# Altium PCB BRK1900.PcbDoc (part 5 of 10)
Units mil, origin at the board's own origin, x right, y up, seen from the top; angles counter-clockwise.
Board outline 8858.27 x 5905.51 mil, 10 copper layers (L1-TOP, L2-GND, L3-SIG1, L4-GND, L5-PWR, L6-PWR, L7-GND, L8-SIG2, L9-GND, L10-BOT), stack 48.824 mil thick; 507 components, 607 nets, 2498 pads, 2210 vias.
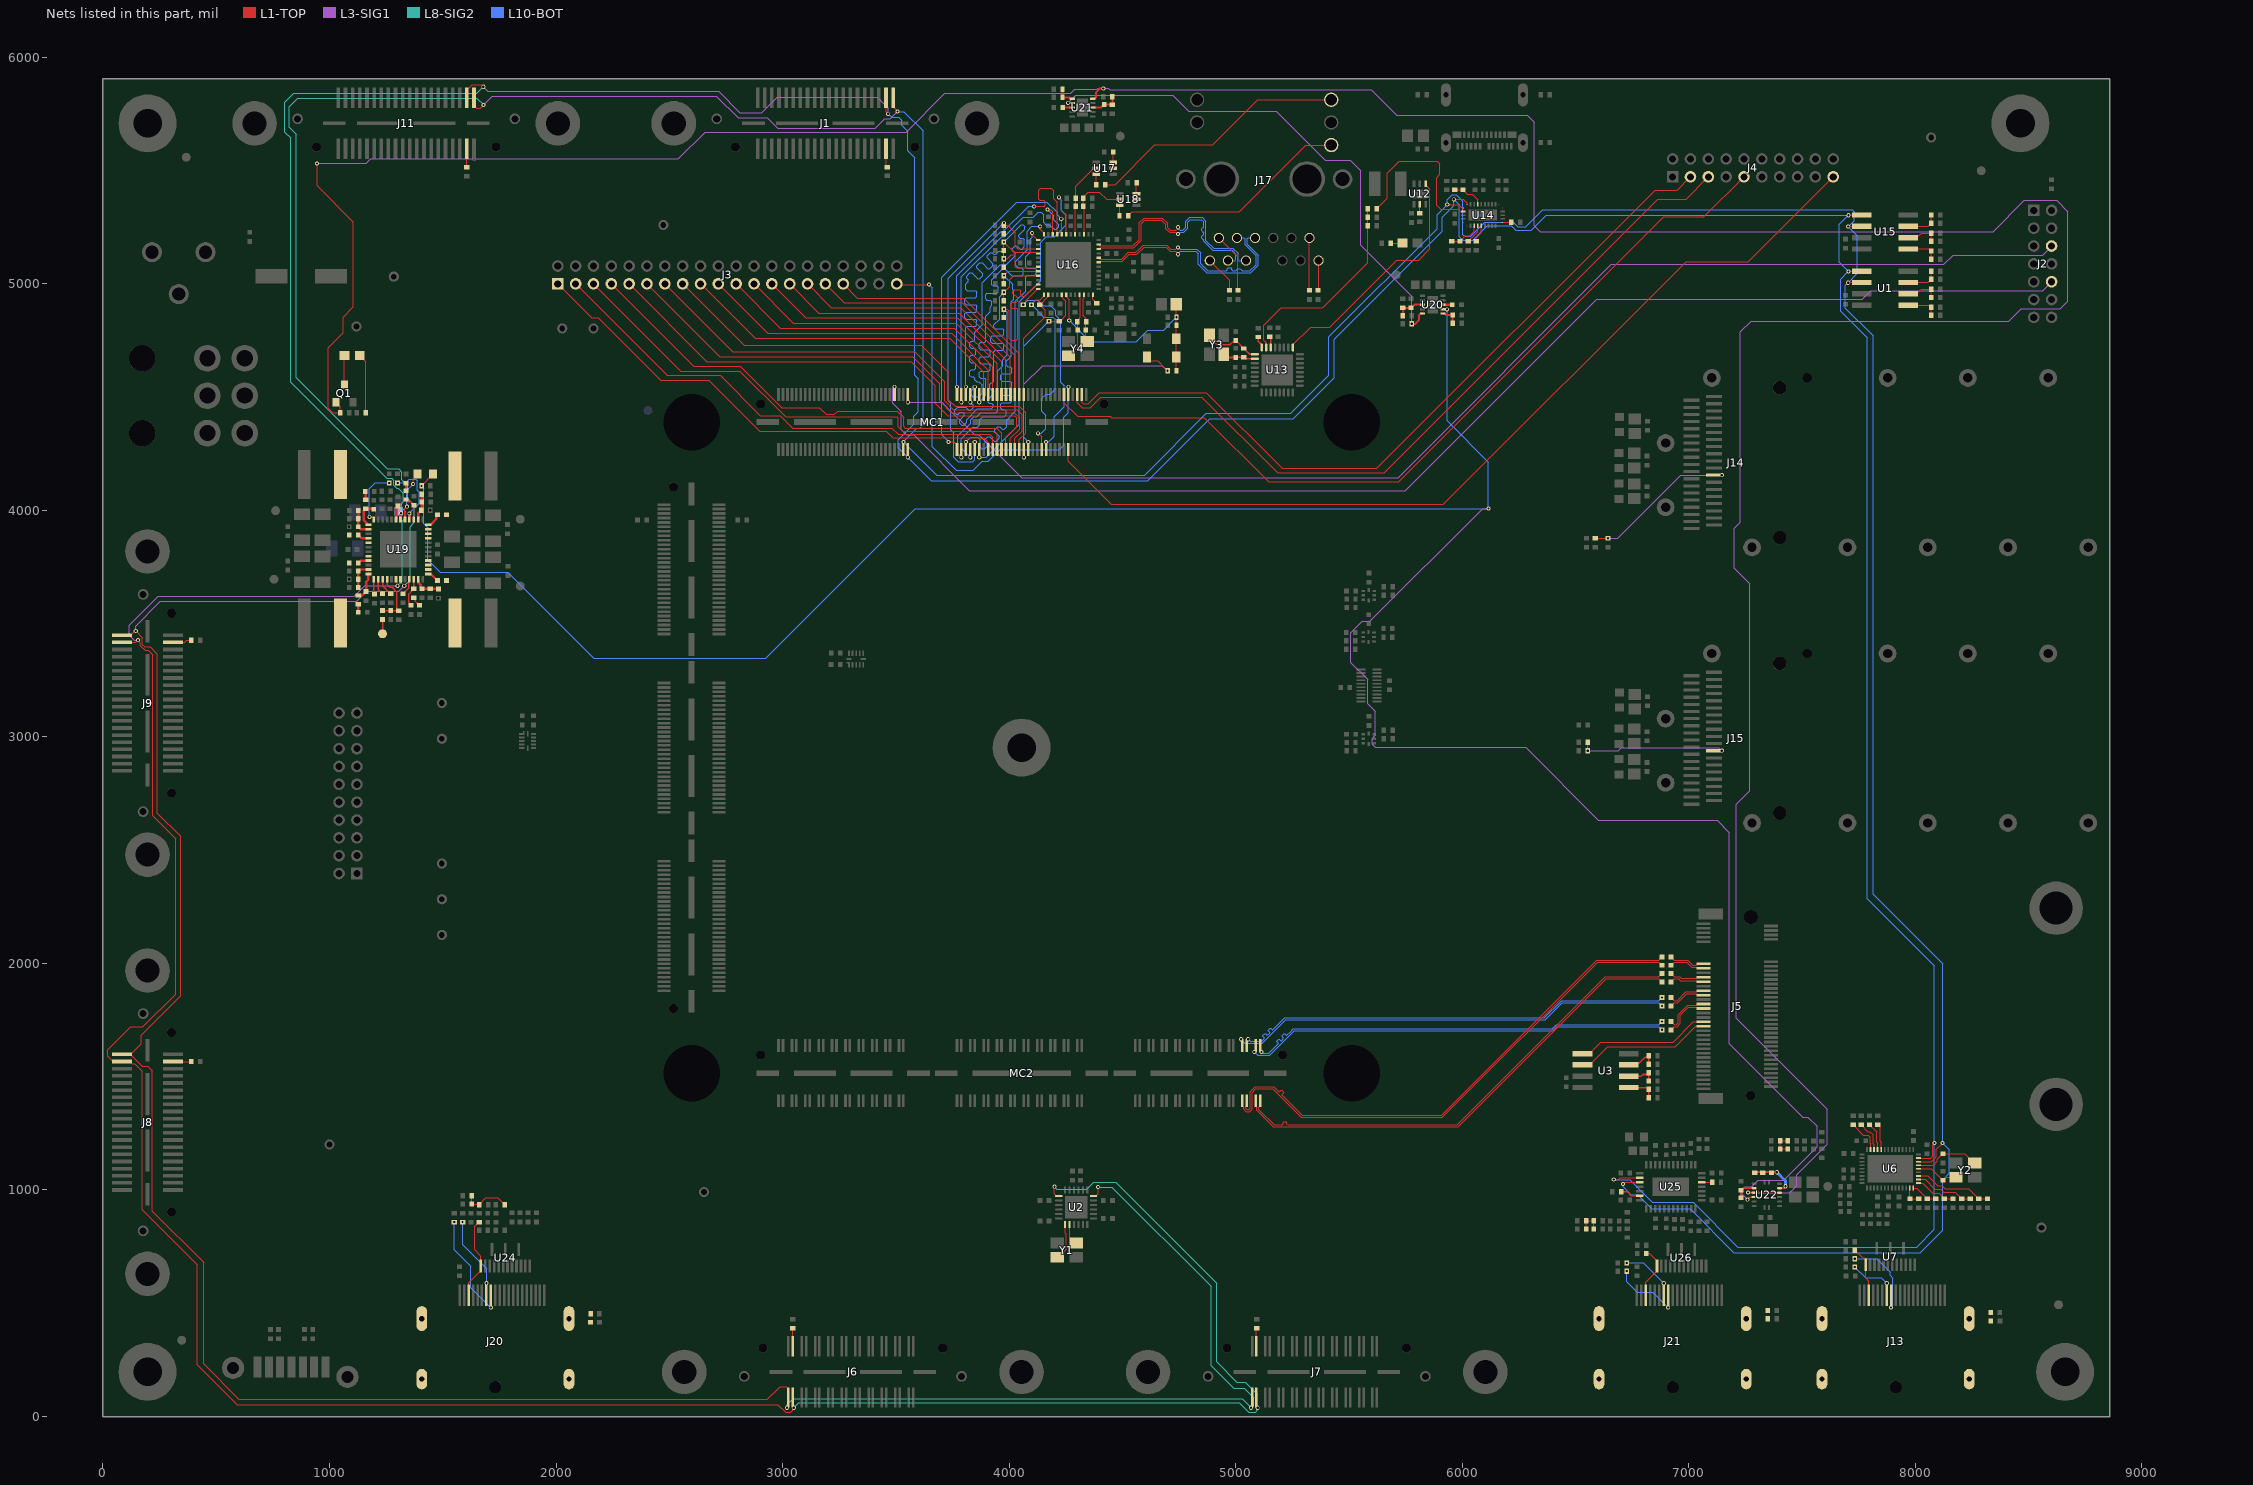
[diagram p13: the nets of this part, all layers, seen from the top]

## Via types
v1: diameter 18, hole 10, L1-TOP to L10-BOT, tented both sides, 2210 vias

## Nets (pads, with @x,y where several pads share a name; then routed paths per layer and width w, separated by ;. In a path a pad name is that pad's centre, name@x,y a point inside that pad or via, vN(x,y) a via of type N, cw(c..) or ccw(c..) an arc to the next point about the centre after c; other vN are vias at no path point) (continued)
ETH_TXRX_C_N: J17.2 U16.8 | length 1009.5
  L1-TOP w3.3: U16.8@4395.76,5114.81 4401.1,5109.47 4496.47,5109.47 4526,5139 4559.81,5139 4574.29,5153.48 4587.54,5166.73 4591.81,5171 4697,5171 4714.52,5153.48 4736.72,5153.48 v1@4746,5162.76
  L10-BOT w3.3: v1@4746,5162.76 4755.28,5153.48 4828.24,5153.48 4845,5136.73 4845,5089.25 4876.11,5058.15 4957.91,5058.15 4959.57,5058.15 4963.63,5062.21 4963.63,5066.09 4967.69,5070.15 4979.87,5070.15 4983.93,5066.09 4983.93,5062.21 4987.99,5058.15 5000.17,5058.15 5004.23,5062.21 5004.23,5063.45 5008.29,5067.51 5020.47,5067.51 5024.53,5063.45 5024.53,5062.21 5028.59,5058.15 5050,5058.15 5063.15,5058.15 5090,5085 5090,5123.27 5041.5,5171.77 5041.5,5198 5036.9,5202.6 J17.2@5006,5202.6
  other v1: 4746,5160.56
ETH_TXRX_C_P: J17.3 U16.7 | length 1000.7
  L1-TOP w3.3: U16.7@4395.76,5095.12 4401.1,5100.47 4500.19,5100.47 4529.73,5130 4563.54,5130 4595.54,5162 4693.27,5162 4710.79,5144.48 4736.72,5144.48 v1@4746,5135.2
  L10-BOT w3.3: v1@4746,5135.2 4755.28,5144.48 4824.52,5144.48 4836,5133 4836,5085.53 4872.38,5049.15 5066.87,5049.15 5099,5081.27 5099,5127 5050.5,5175.5 5050.5,5198 5055.1,5202.6 J17.3@5086,5202.6
  other v1: 4746,5130.8
ETH_TXRX_D_N: J17.9 U16.11 | length 972
  L1-TOP w3.3: U16.11@4395.76,5173.86 4401.1,5168.52 4546.79,5168.52 4574,5195.73 4574,5268.8 4595.71,5290.51 4676.13,5290.51 4700,5266.64 4700,5248 4711.84,5236.16 4736.72,5236.16 v1@4746,5245.44
  L10-BOT w3.3: v1@4746,5245.44 4755.28,5236.16 4767,5236.16 4780,5249.16 4780,5271.73 4780,5276.13 4796.86,5292.99 4801.26,5292.99 4846.74,5292.99 4852.98,5292.99 4869,5276.97 4869,5270.73 4869,5191 4903,5157 4987.73,5157 5010.5,5134.23 5010.5,5106 5013.9,5102.6 J17.9@5046,5102.6
  other v1: 4746,5249.84
ETH_TXRX_D_P: J17.8 U16.10 | length 980.8
  L1-TOP w3.3: U16.10@4395.76,5154.18 4401.1,5159.52 4550.52,5159.52 4583,5192 4583,5265.07 4599.44,5281.51 4672.4,5281.51 4691,5262.91 4691,5244.27 4708.11,5227.16 4736.72,5227.16 v1@4746,5217.88
  L10-BOT w3.3: v1@4746,5217.88 4755.28,5227.16 4770.73,5227.16 4789,5245.43 4789,5272.4 4800.58,5283.99 4849.25,5283.99 4860,5273.24 4860,5268 4860,5250.05 4856.74,5246.79 4853.26,5246.79 4850,5243.53 4850,5233.75 4853.26,5230.49 4856.74,5230.49 4860,5227.23 4860,5217.45 4856.74,5214.19 4853.77,5214.19 4850.51,5210.93 4850.51,5201.15 4853.77,5197.89 4856.74,5197.89 4860,5194.63 4860,5192.54 4860,5187.27 4899.27,5148 4984,5148 5001.5,5130.5 5001.5,5106 4998.1,5102.6 J17.8@4966,5102.6
  other v1: 4746,5220.08
FPX1301_RXN0: C15.1 MC2.120 | length 2145.7
  L1-TOP w3.3: MC2.120@5108.27,1394.09 5108.27,1371.48 5102.92,1366.14 5102.92,1355 5169.93,1288 5194,1288 5207.88,1288 5210.33,1290.45 5210.33,1299.1 5212.77,1301.54 5224.18,1301.54 5226.63,1299.1 5226.63,1290.45 5229.07,1288 5247.02,1288 5979.27,1288 6632.27,1941 6867.92,1941 C15.1@6881.92,1955
FPX1301_RXN0_C: C15.2 J5.51 | length 154.9
  L1-TOP w3.3: C15.2@6922.08,1955 6936.08,1941 6959.73,1941 6967.09,1933.63 7035.94,1933.63 7041.29,1938.98 J5.51@7065.94,1938.98
FPX1301_RXN1: C17.1 MC2.116 | length 2325.1
  L1-TOP w3.3: MC2.116@5049.21,1394.09 5049.21,1371.31 5043.87,1365.97 5043.87,1360 5050.22,1353.65 5057.65,1353.65 5064,1360 5064,1433.73 5085.64,1455.37 5168.63,1455.37 5186.5,1437.5 5190.32,1433.68 5193.78,1433.68 5199.9,1439.79 5203.36,1439.79 5211.43,1431.73 5211.43,1428.27 5205.31,1422.15 5205.31,1418.69 5218,1406 5294,1330 5909.27,1330 6594.27,2015 6867.92,2015 C17.1@6881.92,2029
FPX1301_RXN1_C: C17.2 J5.57 | length 161.1
  L1-TOP w3.3: C17.2@6922.08,2029 6936.08,2015 6995.69,2015 7018,1992.69 7035.77,1992.69 7041.11,1998.03 J5.57@7065.94,1998.03
FPX1301_RXP0: C14.1 MC2.118 | length 2139.2
  L1-TOP w3.3: MC2.118@5088.58,1394.09 5088.58,1370.89 5093.92,1365.54 5093.92,1351.27 5153.2,1292 5166.2,1279 5983,1279 5996,1292 6636,1932 6867.92,1932 C14.1@6881.92,1918
FPX1301_RXP0_C: C14.2 J5.49 | length 154.9
  L1-TOP w3.3: C14.2@6922.08,1918 6936.08,1932 6956,1932 6963.37,1924.63 7035.71,1924.63 7041.05,1919.29 J5.49@7065.94,1919.29
FPX1301_RXP1: C16.1 MC2.114 | length 2318.7
  L1-TOP w3.3: MC2.114@5029.53,1394.09 5029.53,1371.06 5034.87,1365.71 5034.87,1356.27 5046.49,1344.65 5061.38,1344.65 5073,1356.27 5073,1430 5089.37,1446.37 5164.9,1446.37 5268.27,1343 5290.27,1321 5913,1321 5935,1343 6598,2006 6867.92,2006 C16.1@6881.92,1992
FPX1301_RXP1_C: C16.2 J5.55 | length 161.1
  L1-TOP w3.3: C16.2@6922.08,1992 6936.08,2006 6991.96,2006 7014.27,1983.69 7035.54,1983.69 7040.88,1978.35 J5.55@7065.94,1978.35
FPX1301_TXN0: C11.1 MC2.119 | length 1871.5
  L10-BOT w3.3: v1(5114.17,1609.4) 5120.61,1602.97 5146.24,1602.97 5186.64,1643.36 5187.8,1644.53 5187.8,1647.99 5181.69,1654.11 5181.69,1657.56 5189.75,1665.63 5193.21,1665.63 5199.33,1659.51 5202.79,1659.51 5210.85,1667.58 5210.85,1671.04 5204.74,1677.16 5204.74,1680.62 5212.8,1688.68 5216.26,1688.68 5222.38,1682.57 5225.84,1682.57 5233.3,1690.03 5238.27,1695 5255.27,1712 6397.27,1712 6415.28,1730.01 6867.92,1730.01 v1(6881.92,1744.01)
FPX1301_TXN0_C: C11.2 J5.39 | length 208
  L1-TOP w3.3: C11.2@6922.08,1744.01 6936.08,1730.01 6945.04,1730.01 6954,1738.97 6954,1774.36 6995.16,1815.52 7036.38,1815.52 7041.72,1820.87 J5.39@7065.94,1820.87
FPX1301_TXN1: C13.1 MC2.115 | length 1952.7
  L10-BOT w3.3: v1(5055.12,1665.4) 5063.52,1657 5114.27,1657 5125.64,1668.36 5126.8,1669.53 5126.8,1672.99 5120.69,1679.11 5120.69,1682.56 5128.75,1690.63 5132.21,1690.63 5138.33,1684.51 5141.79,1684.51 5149.85,1692.58 5149.85,1696.04 5143.74,1702.16 5143.74,1705.62 5151.8,1713.68 5155.26,1713.68 5161.38,1707.57 5164.84,1707.57 5174.64,1717.36 5206.27,1749 5217.27,1760 6363.27,1760 6438.78,1835.5 6867.92,1835.5 v1(6881.92,1849.5)
FPX1301_TXN1_C: C13.2 J5.45 | length 168.1
  L1-TOP w3.3: C13.2@6922.08,1849.5 6936.08,1835.5 6948.5,1835.5 6987.58,1874.58 7035.77,1874.58 7041.11,1879.92 J5.45@7065.94,1879.92
FPX1301_TXP0: C10.1 MC2.117 | length 1864.1
  L10-BOT w3.3: v1(5082.68,1609.4) 5098.11,1593.97 5149.97,1593.97 5259,1703 6401,1703 6419.01,1721.01 6867.92,1721.01 v1(6881.92,1707.01)
FPX1301_TXP0_C: C10.2 J5.37 | length 208
  L1-TOP w3.3: C10.2@6922.08,1707.01 6936.08,1721.01 6948.77,1721.01 6963,1735.24 6963,1770.63 6998.89,1806.52 7035.53,1806.52 7040.87,1801.18 J5.37@7065.94,1801.18
FPX1301_TXP1: C12.1 MC2.113 | length 1945.2
  L10-BOT w3.3: v1(5023.62,1665.4) 5041.02,1648 5118,1648 5221,1751 6367,1751 6442.5,1826.5 6867.92,1826.5 v1(6881.92,1812.5)
FPX1301_TXP1_C: C12.2 J5.43 | length 168.1
  L1-TOP w3.3: C12.2@6922.08,1812.5 6936.08,1826.5 6952.23,1826.5 6991.31,1865.58 7035.62,1865.58 7040.96,1860.24 J5.43@7065.94,1860.24
FPX_EEPROM_SCL: J5.29 U3.6 | length 605.2
  L1-TOP w5: U3.6@6531.24,1552.15 6563.7,1552.15 6643.55,1632 6941,1632 7031.44,1722.44 J5.29@7065.94,1722.44
FPX_EEPROM_SDA: J5.31 U3.5 | length 592.7
  L1-TOP w5: U3.5@6531.24,1602.15 6561.15,1602.15 6612,1653 6931,1653 7020.13,1742.13 J5.31@7065.94,1742.13
GIGE_INT_B: MC1.91 R107.1 U16.38 | length 505.2
  L1-TOP w5: MC1.91@4064.96,4511.42 4064.96,4759.96 4160,4855 4160,4883.69 R107.1@4136,4907.69 4136.69,4907.69 4173.32,4944.32 U16.38@4173.32,4951.42
GIGE_LED1: R110.1 R115.2 U16.17 U17.2 | length 335.9
  L1-TOP w5: U16.17@4291.43,5219.14 4291.43,5338.82 R110.1@4294.74,5342.14 R115.2@4294.74,5378.14 4294.74,5430.74 4374,5510 U17.2@4384.83,5510
GIGE_LED2: R111.1 R116.2 U16.15 U18.2 | length 347.8
  L1-TOP w5: U16.15@4330.8,5219.14 4330.8,5338.4 R111.1@4327.06,5342.14 R116.2@4327.06,5378.14 4327.06,5382.06 4350,5405 4398,5405 4430,5373 U18.2@4487.6,5373
GIGE_LED_MODE: MC1.94 R108.1 R114.2 U16.41 | length 770.5
  L1-TOP w5: R108.1@4176,4834.69 v1(4176.14,4834.82) R114.2@4222.06,4834.82 4224.03,4834.82 4231.37,4842.17 4251.06,4861.86 4251.06,4923.14 4234.8,4939.4 4234.8,4949 U16.41@4232.37,4951.42
  L10-BOT w5: v1(4084.65,4302.11) 4065,4321.76 4065,4723.69 v1(4176.14,4834.82)
GIGE_MDC: MC1.102 R105.1 U16.36 | length 905.1
  L1-TOP w4.55: v1(4062,4907.69) 4073,4918.69 4073,4926 4124.01,4977.01 U16.36@4128.04,4977.01
  L10-BOT w4.55: v1(4062,4907.69) 4081.46,4927.14 4126.86,4927.14 4151,4903 4184,4903 4205,4882 4205,4861 4229,4837 4229,4724 4229,4566.1 4244,4551.1 4244,4457 4200,4413 4200,4327 4175.11,4302.11 v1(4163.39,4302.11)
GIGE_MDIO: MC1.100 R106.1 U16.37 | length 852
  L1-TOP w4.55: v1(4099,4907.69) 4120.87,4929.55 4137.55,4929.55 4153.63,4945.63 U16.37@4153.63,4951.42 ; v1(4127.84,4340.27) 4143.7,4324.41 MC1.100@4143.7,4268.11
  L10-BOT w4.55: v1(4099,4907.69) 4153.69,4853 4193,4853 4203,4843 4203,4535 4181,4513 4163,4513 4144,4494 4144,4438 4161,4421 4161,4360 4141.27,4340.27 v1(4127.84,4340.27)
GIGE_RESET_B: D3.2 MC1.92 R117.1 | length 1117.1
  L1-TOP w4.55: D3.2@4608.72,4676.57 4624.72,4660.57 4655.6,4660.57 4690.29,4625.89 4692.26,4625.89 4699.6,4618.54 v1(4699.6,4616.57)
  L3-SIG1 w4.05: v1(4064.96,4234.11) 4064.96,4555.96 4148,4639 4677.17,4639 v1(4699.6,4616.57)
GIGE_RX_CLK: MC1.64 R91.1 R99.2 U16.35 | length 1452.9
  L1-TOP w4.55: R99.2@3977.17,4851.42 v1(3977.17,4888.42) 3991.58,4888.42 4001,4879 4001,4759 4009,4751 4032,4751 4038,4757 4038,4887 4033,4892 4015,4892 4008,4899 4008,4913 4013,4918 4032,4918 4038,4924 4038,4938.04 4017,4959.04 4017,4966 4026,4975 4046,4975 4052,4969 4052,4952 4058,4946 4070,4946 4120.7,4996.7 U16.35@4128.04,4996.7
  L10-BOT w4.55: v1(3789.37,4234.11) 3774,4249.48 3774,4329 3830,4385 3830,4400 3844,4414 3857.16,4414 3874.58,4431.42 3940.42,4431.42 3949,4440 3949,4616 3971,4638 3971,4666 3992,4687 3992,4873.59 v1(3977.17,4888.42)
GIGE_RX_DV: MC1.67 R90.1 R98.2 U16.33 | length 1416
  L1-TOP w4.55: R98.2@3977.17,4925.42 v1(3977.17,4962.42) 4002,4987.25 4002,5018 4020.07,5036.07 U16.33@4128.04,5036.07
  L10-BOT w4.55: v1(3828.74,4477.42) 3841,4465.16 3841,4453 3831,4443 3821,4443 3808,4456 3773,4456 3761,4444 3761,4429 3766,4424 3774.5,4424 3784.5,4434 3797,4434 3803,4428 3803,4420 3782,4399 3782,4384 3791,4375 3799,4375 3813,4389 3813,4401 3860,4448 3921,4448 3930,4457 3930,4467 3923,4474 3912,4474 3908.19,4477.81 3908.19,4489.81 3933,4514.62 3933,4519.13 3933,4525.98 3926.69,4532.29 3921.45,4532.29 3915.14,4538.6 3915.14,4557.53 3921.45,4563.84 3926.69,4563.84 3933,4570.15 3933,4603.97 3933,4693.33 3933,4700.81 3939.31,4707.12 3971.04,4707.12 3977.35,4713.43 3977.35,4732.36 3971.04,4738.67 3926.16,4738.67 3919.85,4744.98 3919.85,4763.91 3926.16,4770.23 3971.04,4770.23 3977.35,4776.53 3977.35,4795.47 3971.04,4801.77 3939.31,4801.77 3933,4808.08 3933,4810.36 3933,4819 3958,4844 3958,4943.25 v1(3977.17,4962.42)
GIGE_RXD0: MC1.68 R95.1 R103.2 U16.32 | length 1433.7
  L1-TOP w4.55: R103.2@3977.31,4999.68 3977.31,5036.28 v1(3977.17,5036.42) 3996.5,5055.75 U16.32@4128.04,5055.75
  L10-BOT w4.55: v1(3828.74,4234.11) 3787.88,4274.97 3787.88,4315.88 3839,4367 3859,4367 3870,4378 3870,4399.26 3883.87,4413.13 3979.13,4413.13 3988,4422 3988,4436 3988,4438.28 3981.69,4444.59 3970.31,4444.59 3964,4450.9 3964,4469.83 3970.31,4476.14 4005.69,4476.14 4012,4482.45 4012,4501.38 4005.69,4507.69 3970.31,4507.69 3964,4514 3964,4532.93 3970.31,4539.24 4005.69,4539.24 4012,4545.55 4012,4564.48 4005.69,4570.79 3970.31,4570.79 3964,4577.1 3964,4596.03 3970.31,4602.34 4005.69,4602.34 4012,4608.65 4012,4627.58 4005.69,4633.89 3994.31,4633.89 3988,4640.2 3988,4650 3988,4658 4010,4680 4010,4921.65 4021.31,4932.95 4021.31,4969.29 4016,4974.59 4016,4997.59 v1(3977.17,5036.42)
GIGE_RXD1: MC1.65 R94.1 R102.2 U16.31 | length 1420.3
  L1-TOP w4.55: R102.2@3977.07,5073.41 R94.1@3977.07,5110.33 ; v1(3977.17,5110.42) 3991.42,5110.42 4009,5128 4021,5128 4028,5121 4028,5075 4032,5071 4118,5071 4122.44,5075.44 U16.31@4128.04,5075.44
  L10-BOT w4.55: v1(3809.05,4545.42) 3809.05,4772.24 3809.05,4806.06 3815.36,4812.37 3851.94,4812.37 3858.25,4818.68 3858.25,4837.61 3851.94,4843.92 3811.64,4843.92 3805.33,4850.23 3805.33,4869.16 3811.64,4875.47 3851.94,4875.47 3858.25,4881.78 3858.25,4900.71 3851.94,4907.02 3811.64,4907.02 3805.33,4913.33 3805.33,4932.26 3811.64,4938.57 3851.94,4938.57 3858.25,4944.88 3858.25,4963.81 3851.94,4970.12 3815.36,4970.12 3809.05,4976.43 3809.05,4983.72 3809.05,4999.05 3818.5,5008.5 3820.11,5010.11 3820.11,5019.03 3813.48,5025.67 3813.48,5034.59 3826.86,5047.97 3835.79,5047.97 3861.47,5022.29 3870.39,5022.29 3883.78,5035.68 3883.78,5044.6 3858.09,5070.28 3858.09,5079.21 3871.48,5092.59 3880.4,5092.59 3906.09,5066.91 3915.01,5066.91 3928.39,5080.3 3928.39,5089.22 3902.71,5114.9 3902.71,5123.83 3916.1,5137.21 3925.02,5137.21 3931.65,5130.58 3940.58,5130.58 3948,5138 3954,5144 3971,5144 3977.17,5137.83 v1(3977.17,5110.42)
GIGE_RXD2: MC1.69 R93.1 R101.2 U16.28 | length 1480.4
  L1-TOP w4.55: v1(3977.17,5184.42) 3977.32,5184.42 4021.75,5140 4115,5140 4120.51,5134.49 U16.28@4128.04,5134.49 ; R101.2@3977.26,5147.41 R93.1@3977.26,5184.34
  L10-BOT w4.55: v1(3848.42,4545.42) 3832,4528.99 3832,4510 3840,4502 3865,4502 3881,4518 3881,4554 3867.12,4567.88 3857.77,4567.88 3848.42,4577.23 3848.42,4577.75 3848.42,4582.8 3842.11,4589.11 3832.73,4589.11 3826.42,4595.42 3826.42,4614.35 3832.73,4620.66 3846.51,4620.66 3852.82,4626.97 3852.82,4645.9 3846.51,4652.21 3832.73,4652.21 3826.42,4658.52 3826.42,4677.45 3832.73,4683.76 3846.51,4683.76 3852.82,4690.07 3852.82,4709 3846.51,4715.31 3832.73,4715.31 3826.42,4721.62 3826.42,4740.55 3832.73,4746.86 3842.11,4746.86 3848.42,4753.17 3848.42,4787 3881,4819.58 3881,5005 3960,5084 3988,5084 4027.5,5123.5 4027.5,5135.5 4013.75,5149.25 4013.75,5154.75 4026.5,5167.5 4034.5,5167.5 4049,5153 4057,5153 4067,5163 4067,5195.5 4060.5,5202 4048,5202 4042,5208 4042,5215 4069,5242 4069,5253 4062,5260 4052.75,5260 v1(3977.17,5184.42)
GIGE_RXD3: MC1.70 R92.1 R100.2 U16.27 | length 1594.6
  L1-TOP w4.55: R100.2@3977.17,5221.42 R92.1@3977.17,5258.42 3994.58,5258.42 4027,5226 4027,5165 4037.82,5154.18 U16.27@4128.04,5154.18
  L10-BOT w4.55: v1(3848.42,4302.11) 3848.42,4224.42 3839.51,4215.51 3775.49,4215.51 3756,4235 3756,4343 3743,4356 3743,4474 3732,4485 3732,5024.3 v1(3977.16,5269.46)
GIGE_TX_CLK: MC1.71 U16.24 | length 1382.5
  L1-TOP w4.55: v1(4137.04,5253.5) 4137.04,5241.96 4153.63,5225.37 U16.24@4153.63,5219.14
  L10-BOT w4.55: v1(3868.11,4477.42) 3898,4507.31 3898,4575 3898,4577.28 3891.69,4583.59 3873.83,4583.59 3867.52,4589.9 3867.52,4608.83 3873.83,4615.14 3910.45,4615.14 3916.76,4621.45 3916.76,4640.38 3910.45,4646.69 3873.83,4646.69 3867.52,4653 3867.52,4671.93 3873.83,4678.24 3910.45,4678.24 3916.76,4684.55 3916.76,4703.48 3910.45,4709.79 3873.83,4709.79 3867.52,4716.1 3867.52,4735.03 3873.83,4741.34 3891.69,4741.34 3898,4747.65 3898,4757.16 3898,4858 3916,4876 3916,4897 3924,4905 3924,4919 3924,4921.28 3917.69,4927.59 3902.31,4927.59 3896,4933.9 3896,4952.83 3902.31,4959.14 3945.69,4959.14 3952,4965.45 3952,4984.38 3945.69,4990.69 3930.31,4990.69 3924,4997 3924,5010 3924,5019 3969,5064 3983,5064 4012,5035 4055,5035 4063,5043 4063,5065 4056,5072 4040,5072 4029,5083 4029,5099 4080.07,5150.07 4080.07,5233.07 4100.5,5253.5 v1(4137.04,5253.5)
GIGE_TX_EN: MC1.66 U16.25 | length 1404.9
  L1-TOP w4.55: v1(4101.72,5224.88) 4101.72,5217.28 4106.86,5212.14 4125.45,5193.55 U16.25@4128.04,5193.55
  L10-BOT w4.55: v1(3809.05,4302.11) 3830.53,4323.58 3862.42,4323.58 3872,4314 3872,4278 3877,4273 3893,4273 3901.5,4281.5 3903.11,4283.11 3903.11,4292.03 3892.23,4302.91 3892.23,4311.83 3905.62,4325.22 3914.54,4325.22 3934.73,4305.03 3943.65,4305.03 3957.04,4318.42 3957.04,4327.34 3936.85,4347.53 3936.85,4356.45 3950.24,4369.84 3959.16,4369.84 3970.04,4358.96 3978.96,4358.96 3982.25,4362.25 3990,4370 3990,4399 4028,4437 4028,4922.67 4073,4967.67 4073,4998 4073,5031.83 4079.31,5038.14 4113.69,5038.14 4120,5044.45 4120,5063.38 4113.69,5069.69 4079.31,5069.69 4073,5076 4073,5096 4073,5119 4093.54,5139.54 4093.54,5197.54 4101.72,5205.72 v1(4101.72,5224.88)
GIGE_TXD0: MC1.72 U16.19 | length 1534.7
  L1-TOP w4.55: v1(4220,5382) 4233,5369 4233,5321 4252.06,5301.94 U16.19@4252.06,5219.14
  L10-BOT w4.55: v1(3868.11,4234.11) 3898.11,4234.11 4045,4381 4045,4920 4139,5014 4139,5183 4165,5209 4202,5209 4251,5258 4251,5304 4231,5324 4231,5371 v1(4220,5382)
GIGE_TXD1: MC1.62 U16.20 | length 1574.2
  L1-TOP w4.55: v1(3733.02,4302.37) 3756.63,4302.37 3769.68,4289.32 MC1.62@3769.68,4268.11 ; v1(4230.24,5286.89) 4232.37,5284.75 U16.20@4232.37,5219.14
  L10-BOT w4.55: v1(3733.02,4302.37) 3702,4333.38 3702,5029 4034,5361 4167,5361 4212.5,5315.5 4212.5,5304.63 v1(4230.24,5286.89)
GIGE_TXD2: MC1.61 U16.21 | length 1372.1
  L1-TOP w4.55: v1(4110.64,5341.47) 4154.32,5341.47 4154.39,5341.39 4160,5347 4160,5362 4152,5370 4134.52,5370 4130.52,5374 4130.52,5413.52 4139,5422 4186,5422 4198,5410 4198,5375 4212.69,5360.31 U16.21@4212.69,5219.14
  L10-BOT w4.55: v1(3769.68,4545.42) 3769.68,5036.68 3963,5230 3972.25,5230 4083.64,5341.39 4083.72,5341.47 v1(4110.64,5341.47)
GIGE_TXD3: MC1.63 U16.22 | length 1380.1
  L1-TOP w4.55: v1(4169.85,5327.78) 4183.22,5327.78 4193,5318 U16.22@4193,5219.14
  L10-BOT w4.55: v1(3789.37,4477.42) 3789.37,5031.37 3967,5209 3977.9,5209 4062.9,5294 4107,5294 4128,5315 4141,5315 4152,5304 4152,5271 4162,5261 4178,5261 4199,5240 4208,5240 4220,5252 4220,5261 4197,5284 4197,5300.64 v1(4169.85,5327.78)
NetC37_2: C37.2 J13.SHELL1 J13.SHELL2 J13.SHELL3 J13.SHELL4 R27.2
NetC38_1: C38.1 U6.5 Y2.3 | length 191.9
  L1-TOP w5: U6.5@8014.13,1093.63 8071.4,1093.63 C38.1@8121.77,1043.26 8134.28,1055.76 Y2.3@8180.04,1055.76
NetC39_1: C39.1 U6.6 Y2.1 | length 292.1
  L1-TOP w5: U6.6@8014.13,1109.38 8080.89,1109.38 8097.77,1126.26 8097.77,1135.26 C39.1@8121.77,1159.26 8217.77,1159.26 8258.28,1118.76 Y2.1@8263.5,1118.76
NetC77_2: C77.2 R75.2 U13.26 Y3.1 | length 145.6
  L1-TOP w7: Y3.1@4947.41,4688.87 4961.49,4674.79 C77.2@5000.41,4674.79 5000.8,4675.18 R75.2@5036.41,4675.18 5042.32,4669.27 U13.26@5084.54,4669.27
NetC78_2: C78.2 R75.1 U13.25 Y3.3 | length 257.6
  L1-TOP w7: Y3.3@4884.42,4772.33 4904.54,4752.21 4904.54,4743.74 4917.41,4730.87 4974.41,4730.87 4986.59,4743.05 4993.08,4743.05 4999.82,4749.79 C78.2@5000.41,4749.79 5007.15,4743.05 5007.91,4743.05 5028.1,4722.86 5028.1,4720.89 5034.44,4714.55 R75.1@5036.41,4714.55 5038.38,4714.55 5044.72,4708.21 5044.72,4706.24 5062.01,4688.95 U13.25@5084.54,4688.95
NetC106_2: C106.2 J17.12 | length 132.8
  L1-TOP w5: C106.2@5363,4971.08 5366,4974.08 J17.12@5366,5102.6
NetC107_2: C107.2 J17.6 | length 231.5
  L1-TOP w5: C107.2@5326,4971.08 J17.6@5326,5202.6
NetC108_2: C108.2 J17.1 | length 266.3
  L1-TOP w5: J17.1@4926,5202.6 5010,5118.6 C108.2@5010,4971.08
NetC109_2: C109.2 J17.7 | length 167.6
  L1-TOP w5: J17.7@4886,5102.6 4973,5015.6 C109.2@4973,4971.08
NetC110_1: C110.1 R113.2 U16.45 Y4.1 | length 296.9
  L1-TOP w5: Y4.1@4262.06,4682.14 4267.82,4682.14 4288.94,4703.26 4288.94,4709.02 4303.14,4723.22 C110.1@4303.14,4797.14 4303.14,4831.38 R113.2@4301.37,4833.14 4308.72,4840.48 4308.72,4847.8 4314.06,4853.14 4314.06,4935.14 4311.11,4938.08 U16.45@4311.11,4951.42
NetC111_1: C111.1 R113.1 U16.46 Y4.3 | length 215.5
  L1-TOP w5: U16.46@4330.8,4951.42 4330.8,4937.88 4327.06,4934.14 4327.06,4859.14 4337.98,4848.22 4337.98,4833.14 C111.1@4337.98,4797.14 4337.98,4752.68 Y4.3@4345.52,4745.13
NetC112_2: C112.2 D2.1 D3.1 R117.2 R118.1 R119.2 U16.42 | length 969.2
  L1-TOP w5: U16.42@4252.06,4951.42 4252.19,4951.29 4252.19,4943.7 4265.62,4930.27 v1(4265.62,4838.62) ; C112.2@4738.75,4910.57 4738.75,4852.8 v1(4738.97,4852.57) R117.2@4738.97,4616.57
  L10-BOT w5: v1(4265.62,4838.62) 4359.25,4745 4562,4745 4613,4796 4682.39,4796 v1(4738.97,4852.57)
NetC113_2: C113.2 U19.18 | length 29
  L1-TOP w11: U19.18@1313.43,3959.53 1313.43,3983.59 1315.58,3985.74 v1(1315.58,3987.64)
NetC114_2: C114.2 U19.19 | length 64.8
  L1-TOP w11: U19.19@1294.15,3959.93 U19.19@1293.74,3959.53 1293.74,4008.38 1297.67,4012.3 1297.67,4014.82 1302.4,4019.56 C114.2@1302.99,4019.56
NetC118_1: C118.1 U19.1 | length 53.7
  L1-TOP w11: U19.1@1435.47,3719.37 1435.88,3718.96 1447.18,3718.96 1471.18,3694.96 1471.77,3694.96 1476.5,3690.23 C118.1@1476.5,3689.64
NetC118_2: C118.2 L1.1 U19.2 U19.3 U19.4
NetC122_1: C122.1 R122.1 R123.2 U19.47 | length 114.6
  L1-TOP w11: U19.47@1392.17,3695.75 1392.17,3680.9 1401.6,3671.47 1401.75,3671.47 1402.27,3670.95 R123.2@1402.27,3657.67 ; R123.2@1408.58,3653.32 1479.98,3653.32 C122.1@1480.58,3652.72
NetC123_1: C123.1 R124.2 | length 43.7
  L1-TOP w7: R124.2@1372.58,3613.95 1372.91,3613.95 1379.26,3607.61 1379.26,3598.12 C123.1@1389.33,3588.04 ; C123.1@1389.33,3582.45 C123.1@1389.33,3583.04 ; C123.1@1389.33,3587.45 1396.07,3580.72 C123.1@1396.66,3580.72
NetC124_1: C124.1 U19.45 | length 73.6
  L1-TOP w7: C124.1@1325.92,3633.27 1350.39,3657.74 1350.39,3693.34 U19.45@1352.8,3695.75
NetC125_1: C125.1 R124.1 U19.46 | length 134.9
  L1-TOP w7: C125.1@1360.58,3580.64 1359.99,3580.64 1353.26,3587.37 1353.26,3587.96 1350.58,3590.64 1350.58,3631.32 1364.27,3645.01 1364.27,3646.98 R124.1@1370.61,3653.32 ; R124.1@1370.61,3648.32 1372.58,3648.32 1372.48,3648.43 U19.46@1372.48,3695.75
NetC126_1: C126.1 U19.12 | length 67.2
  L1-TOP w11: U19.12@1435.47,3935.91 1435.88,3936.31 1445.26,3936.31 1471.84,3962.9 1471.84,3975.98 C126.1@1476.5,3980.64
NetC126_2: C126.2 L2.1 U19.9 U19.10 U19.11
NetC132_2: C132.2 U19.16 | length 290.3
  L1-TOP w8: v1(1352.58,3986.64) 1352.8,3986.43 U19.16@1352.8,3959.53 U19.16@1353.7,3960.43
  L10-BOT w5: v1(1301,4120.92) 1334.92,4120.92 1351.27,4137.27 1379.91,4137.27 1387.31,4129.87 1387.31,4089.69 1397,4080 1397,4031.06 v1(1352.58,3986.64)
NetC133_1: C133.1 R125.1 R126.2 U19.14 | length 119.4
  L1-TOP w11: U19.14@1392.17,3959.53 1392.17,3987.22 1399.27,3994.33 1401.24,3994.33 1406.9,3999.98 R126.2@1406.9,4071.64
NetC136_1: C136.1 R127.2 | length 33.2
  L1-TOP w7: R127.2@1337.58,4087.4 C136.1@1337.58,4120.56
NetC137_1: C137.1 R127.1 U19.15 | length 109.2
  L1-TOP w7: R127.1@1337.58,4048.03 1347.61,4038 1357.22,4038 C137.1@1372.58,4022.64 1372.48,4022.54 U19.15@1372.48,3959.53
  L1-TOP w8: U19.15@1372.48,3959.53 U19.15@1372.89,3959.93
NetC138_1: C138.1 U19.24 | length 250
  L1-TOP w5: v1(1176.53,3971.72) 1177.78,3970.46 1191.91,3970.46 1195.32,3967.06 U19.24@1195.32,3959.53
  L10-BOT w5: v1(1176.53,3971.72) 1176.53,4095.53 1201.92,4120.92 v1(1264,4120.92)
NetC139_1: C139.1 U19.28 | length 51.5
  L1-TOP w11: C139.1@1126.66,3891.64 1126.66,3891.05 1131.4,3886.31 1131.99,3886.31 1141.45,3876.85 U19.28@1171.69,3876.85
NetC139_2: C139.2 L3.1 U19.29
NetC145_1: C145.1 R128.1 R130.2 U19.26 | length 114.4
  L1-TOP w11: R130.2@1126.27,3999.64 R128.1@1126.27,3963.64 1126.27,3928.03 C145.1@1126.66,3927.64 ; C145.1@1131.99,3922.31 1138.08,3916.22 U19.26@1171.69,3916.22
NetC146_1: C146.1 U19.37 | length 67.4
  L1-TOP w7: U19.37@1195.32,3695.75 1195.32,3632.58 C146.1@1198.29,3629.61
NetC147_1: C147.1 R129.2 | length 38.2
  L1-TOP w11: C147.1@1157.5,4083.64 1159.58,4081.56 R129.2@1159.58,4046.32
NetC148_1: C148.1 R129.1 U19.25 | length 123.2
  L1-TOP w11: U19.25@1171.69,3935.91 1163.82,3935.91 1163.41,3936.31 1163.41,3944.19 1150.92,3956.68 1150.92,3998.29 R129.1@1159.58,4006.95 C148.1@1194.9,4006.95
NetC149_1: C149.1 U19.33 | length 49.8
  L1-TOP w11: C149.1@1126.66,3767.64 1126.66,3768.23 1131.4,3772.96 1132.38,3772.96 1137.84,3778.43 U19.33@1171.69,3778.43
NetC149_2: C149.2 L4.1 U19.32
NetC153_1: C153.1 R132.1 R135.2 U19.35 | length 120.8
  L1-TOP w11: C153.1@1126.27,3731.64 R132.1@1126.27,3695.64 1126.27,3659.95 R135.2@1126.58,3659.64 ; C153.1@1127.06,3731.64 1127.06,3732.23 1131.79,3736.96 1136.14,3736.96 1138.24,3739.06 U19.35@1171.69,3739.06 U19.35@1171.29,3738.65
NetC154_1: C154.1 TP19.1 | length 62.6
  L1-TOP w7: TP19.1@1234.29,3455.53 1234.4,3455.64 C154.1@1234.4,3518.08
NetC154_2: C154.2 C156.2 R134.2 U19.40 | length 236.8
  L1-TOP w7: C154.2@1234.4,3558.24 1235.4,3557.24 1270.4,3557.24 R134.2@1303.43,3557.24 ; U19.40@1254.37,3695.75 1254.37,3671.45 1265.29,3660.53 1276.5,3660.53 1296.29,3640.73 1296.29,3566.35 1297.09,3565.55 1297.09,3563.58 R134.2@1303.43,3557.24 ; R134.2@1305.4,3557.24 R134.2@1303.43,3557.24
NetC155_1: C155.1 R133.2 | length 34.3
  L1-TOP w11: C155.1@1126.21,3550.53 1126.29,3550.61 R133.2@1126.29,3584.84
NetC157_1: C157.1 R133.1 U19.36 | length 124.7
  L1-TOP w11: R133.1@1126.29,3624.21 1128.89,3626.81 1146.68,3626.81 1156.26,3636.39 1156.26,3636.98 1160.99,3641.72 C157.1@1161.58,3641.72 1161.58,3683.64 1171.69,3693.75 U19.36@1171.69,3719.37
NetC161_1: C161.1 R139.1 R142.2 U20.3 | length 125.3
  L1-TOP w9: R142.2@5738.25,4859.77 5738.25,4892.01 5739.94,4893.69 5740.33,4894.09 5775.94,4894.09 5789.85,4908 U20.3@5824.72,4908
NetC163_1: C163.1 R140.1 R143.2 U21.3 | length 125.3
  L1-TOP w9: U21.3@4369.21,5778.23 4404.09,5778.23 4418,5792.14 4453.61,5792.14 4454,5792.54 4455.69,5794.22 R143.2@4455.69,5826.46
NetC166_1: C166.1 R141.1 R147.2 U22.5 | length 202.5
  L1-TOP w9: R147.2@7291,1078.76 7389,1078.76 v1(7389,1078.48) ; U22.5@7404.06,1008.01 7418.53,1008.01 v1(7427,1016.48)
  L10-BOT w12: v1(7389,1078.48) 7427,1040.48 v1(7427,1016.48)
NetC167_2: C167.2 U20.8 | length 39.8
  L1-TOP w9: U20.8@5915.28,4908 5915.28,4907.77 C167.2@5954.86,4907.77
NetC168_2: C168.2 U21.8 | length 39.8
  L1-TOP w9: C168.2@4239.08,5778.46 4278.66,5778.46 U21.8@4278.66,5778.23
NetC177_2: C177.2 R144.1 U22.4 U22.10 | length 217.5
  L1-TOP w5: U22.10@7285.94,1008.01 7291.47,1008.01 7311.16,988.32 U22.4@7404.06,988.32
  L1-TOP w9: R144.1@7231,963.2 C177.2@7231,1000.37 ; C177.2@7235,1000.37 7242.64,1008.01 U22.10@7285.94,1008.01
NetC190_2: C190.2 J20.SHELL1 J20.SHELL2 J20.SHELL3 J20.SHELL4 R155.2
NetC211_2: C211.2 J21.SHELL1 J21.SHELL2 J21.SHELL3 J21.SHELL4 R162.2
NetD1_2: D1.2 R65.1 | length 51.9
  L1-TOP w5: R65.1@5684.69,5180 D1.2@5736.54,5180
NetD4_1: D4.1 Q1.3 | length 127.3
  L1-TOP w5: Q1.3@1065.7,4556.04 1065.7,4682.17 D4.1@1066.54,4683
NetD4_2: D4.2 R138.1 | length 262.9
  L1-TOP w5: D4.2@1133.46,4683 1159.69,4656.78 R138.1@1159.69,4431
NetJ1_4: J1.4 R1.2 | length 82.3
  L1-TOP w5: J1.4@3456.78,5595.86 3456.78,5520.91 R1.2@3462,5515.68
NetJ6_4: J6.4 R14.2 | length 80.5
  L1-TOP w5: J6.4@3044.83,309.84 3044.83,390.15 R14.2@3045,390.32
NetJ7_4: J7.4 R15.2 | length 80.9
  L1-TOP w5: J7.4@5092.08,309.84 5092.08,389.39 R15.2@5093,390.32
NetJ8_4: J8.4 R16.2 | length 80.7
  L1-TOP w4.55: J8.4@309.66,1567 R16.2@390.32,1567
NetJ9_4: J9.4 R17.2 | length 84.2
  L1-TOP w4.55: J9.4@309.65,3417.41 361.41,3417.41 370,3426 R17.2@390.31,3426
NetJ11_4: J11.4 R18.2 | length 81.3
  L1-TOP w4: R18.2@1606,5514.69 1606,5595.48 J11.4@1606.38,5595.86
NetJ13_13: J13.13 R28.2 | length 346.1
  L10-BOT w5: v1(7733.21,697) 7830.53,697 7889.53,638 7889.53,623 7901.53,611 7901.53,488.99 v1(7893.49,480.95)
NetJ13_14: J13.14 R29.2 | length 170.7
  L10-BOT w5: v1(7733.21,660) 7781.21,612 7850.56,612 v1(7874.22,588.34)
NetJ13_18: J13.18 R180.2 U7.1 | length 229.7
  L1-TOP w5: R180.2@7733.53,734 R180.2@7733.21,734 7767.21,700 7774.53,700 7780.91,693.62 U7.1@7780.91,670 7780.91,612.62 7795.28,598.25 J13.18@7795.28,534.65
NetJ14_8: J14.8 R46.2 R47.2 | length 674.7
  L1-TOP w5: R46.2@6587,3877.39 v1(6644,3877.39)
  L3-SIG1 w5: v1(6644,3877.39) 6686.39,3877.39 6964.61,4155.61 v1(7146.43,4155.61)
NetJ15_8: J15.8 R59.2 R60.2 | length 640.6
  L1-TOP w5: v1(6554.69,2938.7) R59.2@6554.69,2976.7
  L3-SIG1 w5: v1(6554.69,2938.7) 6689.7,2938.7 6703,2952 7133.57,2952 v1(7146.43,2939.14)
NetJ17_15: J17.15 R97.1 | length 1024.9
  L1-TOP w5: R97.1@4526.69,5300 4544.69,5318 5016,5318 5310.6,5612.6 J17.15@5422.06,5612.6
NetJ17_17: J17.17 R96.1 | length 1152.5
  L1-TOP w5: R96.1@4424.69,5438 4469,5438 4644,5613 4899,5613 5098.6,5812.6 J17.17@5422.06,5812.6
NetJ20_13: J20.13 R156.2 | length 444.4
  L10-BOT w5: v1(1550.53,858.32) 1550.53,737 1624.53,663 1624.53,568.82 v1(1712.39,480.95)
NetJ20_14: J20.14 R157.2 | length 313.7
  L10-BOT w5: v1(1587.53,858.32) 1587.53,759 1693.12,653.41 v1(1693.12,588.34)
NetJ20_18: J20.18 R181.2 U24.1 | length 367
  L1-TOP w5: J20.18@1614.17,534.65 1614.17,590.65 1667.98,644.46 U24.1@1667.98,665 1667.98,708.54 1640.53,736 1640.53,839 1659.84,858.32 R181.2@1661.53,858.32
NetJ21_13: J21.13 R163.2 | length 277.7
  L10-BOT w5: v1(6726.21,642) 6726.21,594.32 6772.53,548 6842.2,548 v1(6909.24,480.95)
NetJ21_14: J21.14 R164.2 | length 200.9
  L10-BOT w5: v1(6726.21,678) 6800.31,678 v1(6889.97,588.34)
NetJ21_18: J21.18 R182.2 U26.1 | length 232.6
  L1-TOP w5: J21.18@6811.02,534.65 6811.02,592.5 6859.72,641.19 U26.1@6859.72,664.85 6859.72,686.81 6826.53,720 R182.2@6813.21,720
NetR2_1: R2.1 R5.2 U1.1 | length 142.7
  L1-TOP w5: U1.1@7969.36,4906 8063.97,4906 8071.31,4898.66 R2.1@8071.31,4897 R5.2@8071.31,4861
NetR3_1: R3.1 R6.2 U1.2 | length 146.2
  L1-TOP w5: U1.2@7969.36,4956 7977.91,4964.54 8016.54,4964.54 8028,4976 R3.1@8071.31,4976 R6.2@8071.31,4940
NetR4_1: R4.1 R7.2 U1.3 | length 144.9
  L1-TOP w5: U1.3@7969.36,5006 8057.31,5006 8062,5010.69 8063.97,5010.69 8071.31,5018.03 R7.2@8071.31,5020 R4.1@8071.31,5056
NetR8_1: R8.1 R11.2 U3.1 | length 128.2
  L1-TOP w7: U3.1@6735.96,1452.15 6816.57,1452.15 6822.91,1445.81 R11.2@6822.91,1444.15 R8.1@6822.91,1407.15
NetR9_1: R9.1 R12.2 U3.2 | length 129.8
  L1-TOP w7: U3.2@6735.96,1502.15 6789.6,1502.15 6797.29,1509.84 6816.57,1509.84 R12.2@6822.91,1516.18 ; R9.1@6822.91,1481.15 R12.2@6822.91,1516.18 ; R12.2@6822.91,1518.15 R12.2@6822.91,1516.18
NetR10_1: R10.1 R13.2 U3.3 | length 140.4
  L1-TOP w7: U3.3@6735.96,1552.15 6744.27,1560.46 6781.91,1560.46 6807,1585.56 6816.57,1585.56 R13.2@6822.91,1591.9 ; R10.1@6822.91,1555.15 R13.2@6822.91,1591.9 ; R13.2@6822.91,1592.15 R13.2@6822.91,1591.9
NetR19_1: R19.1 U6.19 | length 114.9
  L1-TOP w5: R19.1@7833.77,1287.57 7845,1276.35 7845,1216 7849.76,1211.24 U6.19@7849.76,1179.26
NetR20_1: R20.1 U6.20 | length 123.3
  L1-TOP w5: R20.1@7797.77,1287.57 7829.02,1256.33 7829.02,1209.98 7834.02,1204.98 U6.20@7834.02,1179.26
NetR21_1: R21.1 U6.21 | length 136.9
  L1-TOP w5: R21.1@7761.77,1287.57 7791.35,1258 7800.18,1258 7814.77,1243.41 7814.77,1204.23 7818.27,1200.73 U6.21@7818.27,1179.26
NetR22_1: R22.1 U6.22 | length 152.8
  L1-TOP w5: R22.1@7725.77,1287.57 7771.35,1242 7793,1242 7801.43,1233.57 7801.43,1205.55 7802.52,1204.46 U6.22@7802.52,1179.26
NetR30_1: R30.1 R36.2 U6.45 | length 84.5
  L1-TOP w5: U6.45@7975.75,1008 7975.75,962.97 R30.1@7976.77,961.94 R36.2@8014.77,961.94
NetR31_1: R31.1 R37.2 U6.46 | length 118.4
  L1-TOP w5: U6.46@7991.5,1008 8006.72,1008 R31.1@8052.77,961.94 R37.2@8090.77,961.94
NetR32_1: R32.1 R38.2 U6.1 | length 181.1
  L1-TOP w5: U6.1@8014.13,1030.64 8032.77,1030.64 8078.15,985.26 8105.46,985.26 R32.1@8128.77,961.94 R38.2@8166.77,961.94
NetR33_1: R33.1 R39.2 U6.2 | length 263.6
  L1-TOP w5: U6.2@8014.13,1046.39 8043.77,1046.39 8086.9,1003.26 8112.25,1003.26 8126.25,989.26 8177.46,989.26 R33.1@8204.77,961.94 R39.2@8242.77,961.94
NetR34_1: R34.1 R40.2 U6.3 | length 346.1
  L1-TOP w5: U6.3@8014.13,1062.13 8055.9,1062.13 8098.64,1019.39 8119.55,1019.39 8132.68,1006.26 8236.46,1006.26 R34.1@8280.77,961.94 R40.2@8318.77,961.94
NetR66_2: R66.2 U12.2 | length 39.1
  L1-TOP w5: U12.2@5813,5351.72 5813.06,5351.66 R66.2@5813.06,5312.65
NetR67_1: R67.1 R68.1 R70.1 U13.23 | length 913.2
  L1-TOP w5: U13.23@5134.73,4719.46 5134.73,4740.74 5125,4750.48 5125,4818 5201,4894 5385,4894 5583.31,5092.31 R70.1@5583.31,5257 R68.1@5583.31,5294 R67.1@5583.31,5331
NetR67_2: R67.2 U14.27 | length 755.3
  L1-TOP w5: R67.2@5622.69,5331 5670,5378.31 5670,5489 5722,5541 5891,5541 5902,5530 5902,5483 5887,5468 5887,5347 5905.41,5328.59 5983.41,5328.59 5993.01,5318.99 U14.27@6005.76,5318.99
NetR69_2: R69.2 U13.22 | length 48.4
  L1-TOP w7: R69.2@5150.41,4766.18 5154.42,4762.17 U13.22@5154.42,4719.46
NetR71_1: R71.1 R73.1 U14.3 | length 140.8
  L1-TOP w5: R73.1@5954.41,5188.01 R71.1@5990.41,5188.01 6014.4,5212 6033,5212 6053.01,5232.01 U14.3@6053.01,5256
NetR72_1: R72.1 U14.5 | length 77.1
  L1-TOP w5: R72.1@6062.41,5188.01 6062.41,5204.41 6084.5,5226.5 U14.5@6084.5,5256
NetR74_1: R74.1 U14.4 | length 85.5
  L1-TOP w5: R74.1@6026.41,5188.01 6068.76,5230.35 U14.4@6068.76,5256
NetR76_2: R76.2 U13.24 | length 52.1
  L1-TOP w7: R76.2@5100,4765.31 5100,4746.26 5115.05,4731.21 U13.24@5115.05,4719.46
NetR81_1: R81.1 R83.2 U14.22 | length 140.1
  L1-TOP w5: R81.1@5967.41,5414.64 R83.2@6003.41,5414.64 6022.22,5395.83 6044.17,5395.83 6068.76,5371.24 U14.22@6068.76,5350.49
NetR82_1: R82.1 U14.11 | length 37.7
  L1-TOP w5: U14.11@6178.99,5271.75 6215.83,5271.75 R82.1@6216.41,5272.32
NetR84_1: R84.1 R87.2 U15.1 | length 142.7
  L1-TOP w5: U15.1@7969.36,5154 8063.97,5154 8071.31,5146.66 R84.1@8071.31,5145 R87.2@8071.31,5109
NetR85_1: R85.1 R88.2 U15.2 | length 146.2
  L1-TOP w5: U15.2@7969.36,5204 7977.91,5212.54 8016.54,5212.54 8028,5224 R85.1@8071.31,5224 R88.2@8071.31,5188
NetR86_1: R86.1 R89.2 U15.3 | length 144.9
  L1-TOP w5: U15.3@7969.36,5254 8057.31,5254 8062,5258.69 8063.97,5258.69 8071.31,5266.03 R89.2@8071.31,5268 R86.1@8071.31,5304
NetR96_2: R96.2 U17.3 | length 46.6
  L1-TOP w5: U17.3@4384.83,5484.41 4384.83,5438.49 R96.2@4385.31,5438
NetR97_2: R97.2 U18.3 | length 47.5
  L1-TOP w5: R97.2@4487.31,5300 4487.6,5300.28 U18.3@4487.6,5347.41
NetR104_1: R104.1 U17.5 U17.6 | length 72
  L1-TOP w5: U17.5@4459.63,5510 U17.6@4459.63,5535.59 4459.63,5581.94 R104.1@4459.69,5582
NetR109_1: R109.1 U16.48 | length 45.4
  L1-TOP w5: U16.48@4370.17,4951.42 4370.17,4931.03 4377.75,4923.45 4377.75,4921.48 4385.09,4914.14 R109.1@4387.06,4914.14
NetR112_1: R112.1 U18.5 U18.6 | length 74.1
  L1-TOP w5: U18.5@4562.4,5373 U18.6@4562.4,5398.59 4562.4,5446.72 R112.1@4562.69,5447
NetR120_1: R120.1 U19.39 | length 80.4
  L1-TOP w7: U19.39@1234.69,3695.75 1234.69,3666.82 1261.98,3639.52 1261.98,3637.56 1268.32,3631.21 R120.1@1270.29,3631.21
NetR131_1: R131.1 U19.38 | length 73.7
  L1-TOP w7: U19.38@1215,3695.75 1215,3650.5 1225.98,3639.52 1225.98,3637.55 1232.32,3631.21 R131.1@1234.29,3631.21
NetR136_1: R136.1 R137.1 U20.7 U22.12 | length 11676.7
  L1-TOP w5: v1(1406.31,4108) 1406.31,4109.85 R136.1@1456.46,4160
  L1-TOP w7: v1(7259.69,957.28) 7271.05,968.64 U22.12@7288.9,968.64
  L3-SIG1 w5: v1(6115.9,4008.1) 6090.1,4008.1 5593,3511 5560,3511 5509,3460 5509,3328 5583,3254 5583,3147 5617,3113 5617,3008 5602,2993 5602,2968 5616,2954 6280,2954 6601,2633 7125,2633 7180,2578 7180,1646 7504,1322 7526,1322 7567,1281 7567,1190 7420,1043 7307,1043 7279,1015 7249,1015 7236,1002 7236,980.97 v1(7259.69,957.28)
  L8-SIG2 w5: v1(7259.69,957.28) v1@7259.69,958.06
  L10-BOT w5: v1(1406.31,4108) 1417,4097.31 1417,3940 1434,3923 1434,3782 1490,3726 1788,3726 2167,3347 2925,3347 3586.1,4008.1 v1(6115.9,4008.1) 6115.9,4213.1 5933.29,4395.71 v1(5933.29,4887.3)
NetR136_2: R136.2 U19.17 | length 223.8
  L1-TOP w5: U19.17@1333.11,3959.53 1333.11,4007.62 v1(1341.8,4016.31) ; v1(1369.23,4116) 1369.23,4139.7 R136.2@1389.54,4160
  L10-BOT w5: v1(1341.8,4016.31) 1341.8,4088.57 v1(1369.23,4116)
NetR145_2: R145.2 R150.1 U20.6 | length 81.4
  L1-TOP w9: U20.6@5915.28,4868.63 5922.08,4868.63 5927.94,4862.77 R145.2@5958.25,4862.77 R150.1@5958.25,4826.77
NetR146_2: R146.2 R151.1 U21.6 | length 81.4
  L1-TOP w9: R151.1@4235.69,5859.46 R146.2@4235.69,5823.46 4266,5823.46 4271.86,5817.6 U21.6@4278.66,5817.6
NetR149_1: R149.1 U20.5 U21.7 | length 2290.6
  L1-TOP w9: v1(5777.94,4823.77) 5792.94,4823.77 5809.94,4840.77 5809.94,4862.77 5815.8,4868.63 U20.5@5824.72,4868.63
  L3-SIG1 w5: v1(4260.65,5798.93) 4293.72,5832 4723,5832 4792,5763 5179,5763 5396,5546 5506,5546 5553,5499 5553,5171 5777.94,4946.06 v1(5777.94,4823.77)
NetR153_1: R153.1 R158.2 R168.1 R169.2 | length 208.1
  L1-TOP w5: R169.2@1628.21,975 R168.1@1628.21,938 1657.84,938 R158.2@1660.84,935 1690.84,965 1743.21,965 R153.1@1773.21,935
NetR161_2: R161.2 U25.18 | length 89.9
  L1-TOP w6: R161.2@6701.57,991.59 6730.6,991.59 6746.67,975.51 U25.18@6784.8,975.51
NetR165_2: R165.2 U25.36 | length 44.8
  L1-TOP w5: U25.36@7058.43,1034.57 7103.02,1034.57 R165.2@7103.14,1034.44
NetR170_1: R170.1 R172.2 R174.1 R175.2 | length 104.6
  L1-TOP w5: R174.1@6547.69,828 R175.2@6547.69,864 R170.1@6580.31,864 R172.2@6580.31,828
NetR176_1: R176.1 R177.2 R178.1 R179.2 | length 101.3
  L1-TOP w4: R179.2@7437.31,1181 R177.2@7404.69,1181 R176.1@7404.69,1217 R178.1@7437.31,1217
NetU2_1: U2.1 Y1.3 | length 166.8
  L1-TOP w5: Y1.3@4212.5,703.29 4218.73,703.29 4253.23,737.79 4253.23,801.79 4247.02,808 U2.1@4247.02,847.02
NetU2_2: U2.2 Y1.1 | length 95.4
  L1-TOP w5: U2.2@4266.7,847.02 4266.7,791.26 4291.68,766.28 Y1.1@4295.96,766.28
NetU12_4: U12.4 U13.17 | length 1087.5
  L1-TOP w5: U13.17@5252.84,4719.46 5252.84,4730.84 5330.5,4808.5 5414.5,4808.5 5711,5105 5808,5105 5857.99,5154.99 5857.99,5417.02 5838.59,5436.42 U12.4@5838.59,5442.28
PGOOD: Q1.1 R148.1 U21.5 U22.11 | length 16068.1
  L1-TOP w5: v1(944.88,5531.5) 944.88,5433.07 1106,5271.95 1106,4898 1061,4853 1061,4784 994,4717 994,4451 1014,4431 R148.1@1048.31,4431 1048.31,4457.28 Q1.1@1028.3,4477.3
  L1-TOP w9: U21.5@4369.21,5817.6 4378.14,5817.6 4384,5823.46 4384,5845.46 4401,5862.46 v1(4416,5862.46) ; v1(7262,988.48) 7262.16,988.32 U22.11@7285.94,988.32
  L3-SIG1 w5: v1(944.88,5531.5) 1161.42,5531.5 1181.1,5551.18 1329.18,5551.18 1630.35,5551.18 1632.66,5548.87 1645.5,5548.87 1647.82,5551.18 2539.37,5551.18 2658.19,5670 3545.06,5670 3717.06,5842 4273,5842 4289,5858 4390,5858 4394.46,5862.46 v1(4416,5862.46) 4438.54,5862.46 4444,5857 5599,5857 5711,5745 6287,5745 6319,5713 6319,5255.8 6344.8,5230 8344,5230 8482,5368 8624,5368 8674,5318 8674,4924 8641,4891 8468,4891 8412,4835 7275,4835 7228,4788 7228,3948 7201,3921 7201,3745 7269,3677 7269,2762 7209,2702 7209,1758 7611,1356 7611,1203 7476,1068 7476,1018 7446.48,988.48 v1(7262,988.48)
POR_OVERRIDE: J3.39 MC1.111 | length 1800.8
  L1-TOP w4.84: J3.39@3503.94,5000 3504.19,5000.26 3507.45,4997 v1(3646,4997)
  L10-BOT w4.84: v1(3646,4997) 3661,4982 3661,4282 3766,4177 3841,4177 3881,4217 3908,4217 3958,4267 4221,4267 4241,4287 4241,4411 4261.81,4431.81 v1(4261.81,4545.42)
PS_B500_MIO0: J3.23 MC1.79 | length 1354.7
  L1-TOP w4.55: J3.23@2874.02,5000 3047.02,4827 3767,4827 3946.85,4647.15 MC1.79@3946.85,4511.42
PS_B500_MIO1: J3.13 MC1.88 | length 2033.4
  L1-TOP w4.55: J3.13@2480.31,5000 2779.32,4701 3583,4701 3716,4568 3716,4483 3754,4445 4035,4445 4057,4423 4057,4349 4025.59,4317.59 MC1.88@4025.59,4268.11
PS_B500_MIO2: J3.11 MC1.86 | length 2091.8
  L1-TOP w4.55: J3.11@2401.57,5000 2723.57,4678 3575,4678 3693,4560 3693,4483 3744,4432 4023,4432 4046,4409 4046,4358 4005.91,4317.91 MC1.86@4005.91,4268.11
PS_B500_MIO4: J3.3 MC1.78 | length 2175.8
  L1-TOP w4.55: J3.3@2086.61,5000 2490.61,4596 2725,4596 2902.26,4418.74 2989.26,4418.74 3031.13,4376.87 3044.33,4363.67 3481.33,4363.67 3510,4335 3915,4335 3927.17,4322.83 MC1.78@3927.17,4268.11
PS_B500_MIO5: J3.15 MC1.90 | length 1993.7
  L1-TOP w4.55: J3.15@2559.06,5000 2830.06,4729 3612,4729 3732.22,4608.78 3732.22,4488.78 3762,4459 4044,4459 4073,4430 4073,4341 4045.28,4313.28 MC1.90@4045.28,4268.11
PS_B500_MIO7: J3.7 MC1.82 | length 2104
  L1-TOP w4.55: J3.7@2244.09,5000 2608.09,4636 2813,4636 2996,4453 3163,4453 3192.45,4423.55 3228.55,4423.55 3243,4438 3507,4438 3534,4411 3534,4371 3542,4363 3945,4363 3966.54,4341.46 MC1.82@3966.54,4268.11
PS_B500_MIO8: J3.33 MC1.89 | length 1085
  L1-TOP w4.55: J3.33@3267.72,5000 3330.72,4937 3799,4937 4045.28,4690.72 MC1.89@4045.28,4511.42
PS_B500_MIO11: J3.31 MC1.87 | length 1140.3
  L1-TOP w4.55: J3.31@3188.98,5000 3271.98,4917 3793,4917 4025.59,4684.41 MC1.87@4025.59,4511.42
PS_B500_MIO12: J3.21 MC1.77 | length 1406.6
  L1-TOP w4.55: J3.21@2795.28,5000 2990.28,4805 3757,4805 3927.16,4634.83 MC1.77@3927.16,4511.42
PS_B500_MIO13: J3.27 MC1.83 | length 1246.9
  L1-TOP w4.55: J3.27@3031.5,5000 3160.5,4871 3780,4871 3986.22,4664.78 MC1.83@3986.22,4511.42
PS_B500_MIO19: J3.1 MC1.76 | length 2222.3
  L1-TOP w4.55: J3.1@2007.87,5000 2157.94,4849.94 2187.06,4849.94 2462,4575 2674,4575 2899.8,4349.2 3458.8,4349.2 3487,4321 3888,4321 3907.48,4301.52 MC1.76@3907.48,4268.11
PS_B500_MIO20: J3.25 MC1.81 | length 1300.5
  L1-TOP w4.55: J3.25@2952.76,5000 3101.76,4851 3771,4851 3966.54,4655.46 MC1.81@3966.54,4511.42
PS_B500_MIO21: J3.19 MC1.75 | length 1456.6
  L1-TOP w4.55: J3.19@2716.54,5000 2935.54,4781 3746,4781 3907.48,4619.52 MC1.75@3907.48,4511.42
PS_B500_MIO22: J3.29 MC1.85 | length 1194.5
  L1-TOP w4.55: J3.29@3110.24,5000 3215.24,4895 3787,4895 4005.91,4676.09 MC1.85@4005.91,4511.42
PS_B500_MIO23: J3.17 MC1.73 | length 1510.2
  L1-TOP w4.55: J3.17@2637.8,5000 2878.8,4759 3739,4759 3887.79,4610.21 MC1.73@3887.79,4511.42
PS_B500_MIO24: J3.9 MC1.84 | length 2160.9
  L1-TOP w4.55: J3.9@2322.83,5000 2665.83,4657 3568,4657 3674,4551 3674,4472 3729,4417 4024,4417 4033,4408 4033,4369 3986.22,4322.22 MC1.84@3986.22,4268.11
PS_B500_MIO25: J3.5 MC1.80 | length 2144.4
  L1-TOP w4.55: J3.5@2165.35,5000 2550.35,4615 2812,4615 3014.53,4412.47 3504.53,4412.47 3511,4406 3511,4369 3530,4350 3599,4350 3930,4350 3946.85,4333.15 MC1.80@3946.85,4268.11
PS_DONE: J4.9 MC1.109 | length 3740.6
  L1-TOP w5: MC1.109@4242.13,4511.42 4242.13,4475.17 4302.28,4415.01 4445.99,4415.01 4451.55,4409.45 4862.2,4409.45 5145.67,4125.98 5720.47,4125.98 6889.76,5295.28 7066.93,5295.28 J4.9@7244.09,5472.44
PS_ERROR_OUT: J4.3 MC1.117 | length 3415.5
  L1-TOP w4.84: MC1.117@4320.87,4511.42 4320.87,4478.13 4328,4471 4349,4471 4398,4520 4871,4520 5205.96,4185.04 5623.04,4185.04 6851.39,5413.39 6948.82,5413.39 J4.3@7007.87,5472.44
PS_ERROR_STATUS: J4.5 MC1.115 | length 3529.7
  L1-TOP w4.84: MC1.115@4301.18,4511.42 4301.18,4474.82 4322,4454 4359,4454 4405,4500 4851,4500 5185.65,4165.35 5655.35,4165.35 6864.02,5374.02 6988.19,5374.02 J4.5@7086.61,5472.44
PS_I2C0_SCL_3V3: J1.1 J6.1 J7.1 J8.1 J9.1 J11.1 MC1.58 U1.6 U2.12 U6.7 U14.26 U15.6 U19.43 U25.15 | length 30017.7
  L1-TOP w5: J8.1@84.05,1598.51 120.49,1598.51 173,1546 198,1546 218,1526 218,906 444,680 444,232 600,76 2933,76 2989,132 3017,132 3025.15,123.85 J6.1@3025.15,83.86 ; J9.1@84.05,3448.91 122.77,3448.91 141.54,3467.67 v1(144.89,3467.67) 174,3438.56 174,3407 184,3397 208,3397 240,3365 240,2664 343,2561 343,1857 169,1683 169,1646 J8.1@123.98,1600.98 ; U19.43@1313.43,3695.75 1313.43,3685.57 1329.55,3669.45 v1@1329.55,3666.81 ; J11.1@1637.88,5821.46 1637.88,5787.12 1649,5776 1666,5776 v1(1680,5790) ; J1.1@3488.28,5821.46 3488.28,5782.74 3507.04,5763.98 v1(3507.04,5760.62) ; U2.12@4373,973 4382,973 4393.15,984.15 v1(4393.15,1012.78) ; v1(5934.01,5349.93) 5985.07,5349.93 6000.26,5334.74 U14.26@6005.76,5334.74 ; v1(6710,1026) 6718.57,1034.57 U25.15@6784.8,1034.57 ; v1(7704,5005) 7705,5006 U1.6@7764.64,5006 ; v1(7704,5253) 7705,5254 U15.6@7764.64,5254 ; U6.7@8014.13,1125.13 8070.64,1125.13 8092.34,1146.83 8092.34,1178.83 v1(8120.77,1207.26)
  L1-TOP w11: v1@1329.55,3666.81 v1(1330.14,3666.81)
  L3-SIG1 w5: v1(144.89,3467.67) 144.89,3489.19 253.7,3598 1120,3598 1165.19,3643.19 1306.52,3643.19 v1(1330.14,3666.81) ; v1(1680,5790) 1719,5829 2708,5829 2804,5733 2932,5733 2978,5687 3410,5687 3452,5729 3475.42,5729 v1(3507.04,5760.62)
  L8-SIG2 w5: v1(1330.14,3666.81) 1356,3692.67 1356,3928 1375,3947 1375,4022 1346,4051 1346,4109 1320,4135 1320,4169 1305,4184 1256,4184 854,4586 854,5661 823,5692 823,5781 861,5819 1651,5819 v1(1680,5790) ; v1@3021.21,38.86 3021.21,53.55 3046.66,79 5028.31,79 5068.45,38.86 5079,49.4 5079,84 5039,124 4992,124 4891.5,224.5 4891.5,574.5 4453.22,1012.78 v1(4393.15,1012.78)
  L10-BOT w5: v1(3507.04,5760.62) 3535.38,5760.62 3620,5676 3620,4376 3606,4362 3593.35,4362 v1(3533.46,4302.11) 3680.57,4155 4598,4155 4871,4428 5243,4428 5411,4596 5411,4766 5889,5244 5889,5304.92 v1(5934.01,5349.93) 5934.01,5371.44 5956.57,5394 5974,5394 6002.97,5365.03 6002.97,5217.32 6011.06,5209.23 6037.46,5209.23 6100.61,5272.39 6224.62,5272.39 6244.96,5252.06 6280.06,5252.06 6355,5327 7721,5327 7730,5318 7730,5279 v1(7704,5253) 7745,5212 7745,5046 v1(7704,5005) 7692,4993 7692,4893 7815,4770 7815,2305 8120.77,1999.23 v1(8120.77,1207.26) 8150,1178.03 8150,1073.23 8120.77,1044 8120.77,822.77 8022,724 7199,724 7006,917 6837,917 6775,979 6745,979 6710,1014 v1(6710,1026)
  other v1: 3020.11,38.86 5067.35,38.86
PS_I2C0_SDA_3V3: J1.3 J6.3 J7.3 J8.3 J9.3 J11.3 MC1.60 U1.5 U2.19 U6.8 U14.25 U15.5 U19.42 U25.14 | length 30408.4
  L1-TOP w5: J9.3@84.05,3417.41 145.65,3417.41 v1(155.2,3426.95) 155.2,3424.22 165.5,3413.92 165.5,3403.48 186.42,3382.56 199.09,3382.56 220,3361.65 220,2652 321,2551 321,1865 176,1720 123,1720 22,1619 22,1590.83 45.82,1567.01 J8.3@84.05,1567.01 120.99,1567.01 130,1558 141,1558 174,1525 174,912 417,669 417,229 593,53 2979,53 3013,19 3036,19 3044.83,27.83 J6.3@3044.83,83.86 ; U19.42@1293.74,3695.75 1293.74,3688.26 1299.54,3682.46 v1@1299.54,3666.9 ; J11.3@1606.38,5821.46 1606.38,5854.75 1630.63,5879 1670,5879 v1(1679,5870) ; J1.3@3456.78,5821.46 3456.78,5759.86 v1(3466.32,5750.31) ; v1(4200.08,1014.66) 4200.08,982.92 4210,973 U2.19@4219.46,973 ; v1(5963.27,5373.14) 6004.86,5373.14 6021.51,5356.49 U14.25@6021.51,5350.49 ; v1(6669,1046) 6690,1046 6698.25,1054.25 U25.14@6784.8,1054.25 ; v1(7705,5055) 7706,5056 U1.5@7764.64,5056 ; v1(7705,5303) 7706,5304 U15.5@7764.64,5304 ; U6.8@8014.13,1140.87 8068.39,1140.87 8076.52,1149.01 8076.52,1199.01 v1(8084.77,1207.26)
  L1-TOP w11: v1@1299.54,3666.9 v1(1300.13,3666.9)
  L3-SIG1 w5: v1(155.2,3426.95) 139.05,3426.95 117,3449 117,3492.15 244.85,3620 1109.63,3620 1156.53,3666.9 v1(1300.13,3666.9) ; v1(1679,5870) 1699,5850 2718,5850 2812,5756 2909,5756 2976,5823 3419,5823 3466.32,5775.68 v1(3466.32,5750.31)
  L8-SIG2 w5: v1(1300.13,3666.9) 1321,3687.77 1321,3952 1334,3965 1334,3996 1319,4011 1319,4032 1326,4039 1326,4076 1304,4098 1296,4098 1283,4111 1283,4134 1275.5,4141.5 1252.88,4141.5 828,4566.38 828,5645 803,5670 803,5801 843,5841 1650,5841 v1(1679,5870) ; v1@3048.77,38.86 3070.91,61 5016.04,61 5058.04,19 5088.33,19 5096.01,26.68 5096.01,97.99 5042,152 5006,152 4917,241 4917,589 4471,1035 4373,1035 4342,1004 4210.74,1004 v1(4200.08,1014.66)
  L10-BOT w5: v1(3466.32,5750.31) 3481.64,5735 3513,5735 3526,5722 3526,5700 3552,5674 3552,5587 3583.2,5555.8 3583.2,4596.8 3600,4580 3600,4436 3580,4416 3580,4381 3511,4312 3511,4276.26 v1(3553.15,4234.11) 3657.26,4130 4611,4130 4886,4405 5255,4405 5435,4585 5435,4755 5913,5233 5913,5294 5963.27,5344.27 v1(5963.27,5373.14) 5987.49,5348.92 5987.49,5208.71 6004.03,5192.17 6046.95,5192.17 6110.99,5256.21 6217.09,5256.21 6236.3,5237 6305,5237 6371,5303 v1(7705,5303) 7665,5263 7665,5095 v1(7705,5055) 7671,5021 7671,4880 7789,4762 7789,2285 8084.77,1989.23 v1(8084.77,1207.26) 8084.77,825.77 8006.54,747.54 7217.46,747.54 7019.23,945.77 6839.23,945.77 6739,1046 v1(6669,1046)
  other v1: 3049.87,38.86 5097.11,38.86
PS_INIT_B: J4.19 MC1.112 | length 4103.9
  L1-TOP w4.84: MC1.112@4261.81,4268.11 4261.81,4217.19 4451.44,4027.56 5917.32,4027.56 6988.19,5098.43 7263.78,5098.43 J4.19@7637.8,5472.44
PS_JTAG_TCK: J2.6 MC1.59 | length 5610.7
  L3-SIG1 w5: v1(3553.15,4477.42) 3703.58,4477.42 3848,4333 3866,4333 4055,4144 5717,4144 6659,5086 8126,5086 8167,5127 8562,5127 J2.6@8602,5167
PS_JTAG_TDI: J2.10 MC1.53 | length 5780.5
  L3-SIG1 w5: v1(3494.09,4545.42) 3485.41,4536.73 3485.41,4473.59 3523.06,4435.94 3523.06,4356.94 3547,4333 3579,4333 3825,4087 5749,4087 6595,4933 7766,4933 7803,4970 8562.48,4970 J2.10@8602,5009.52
